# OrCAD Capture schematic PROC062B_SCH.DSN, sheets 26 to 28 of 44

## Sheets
26 25. CURRENT MONITORING DEVICES: size C; title: CURRENT MONITORING DEVICES
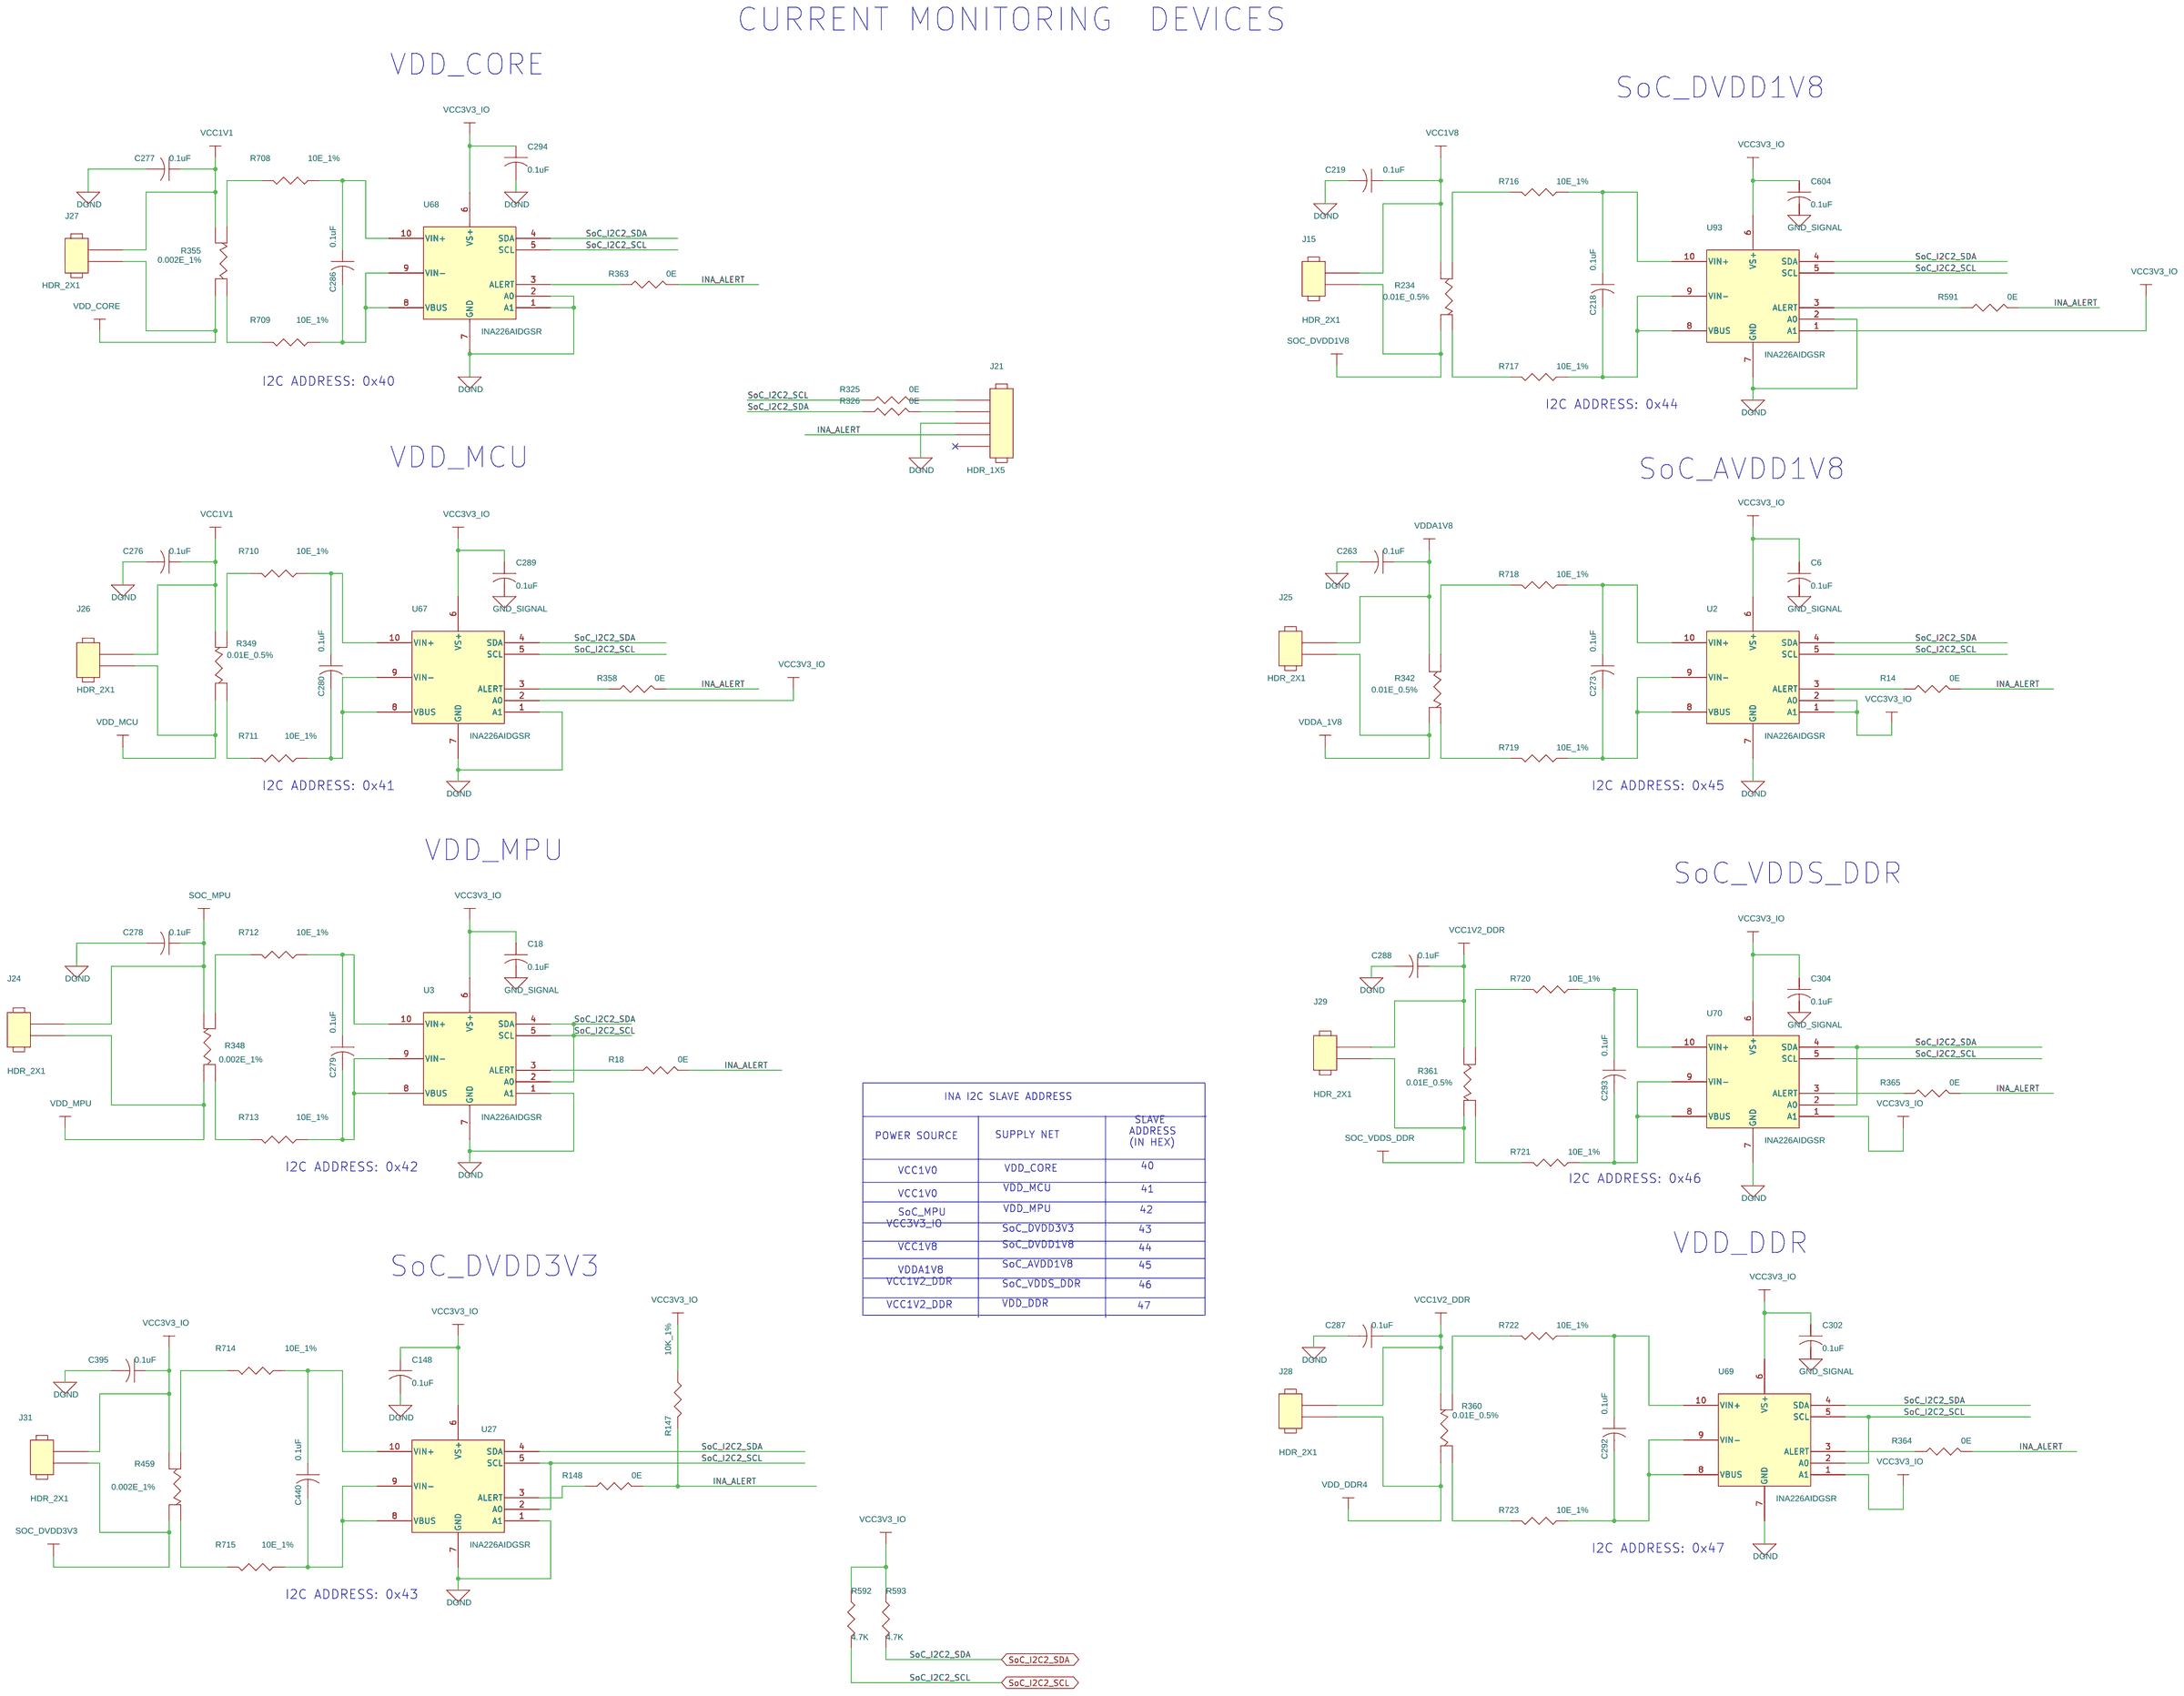
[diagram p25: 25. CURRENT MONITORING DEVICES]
27 26. XDS110 DEBUGGER: size C; title: XDS110 DEBUGGER
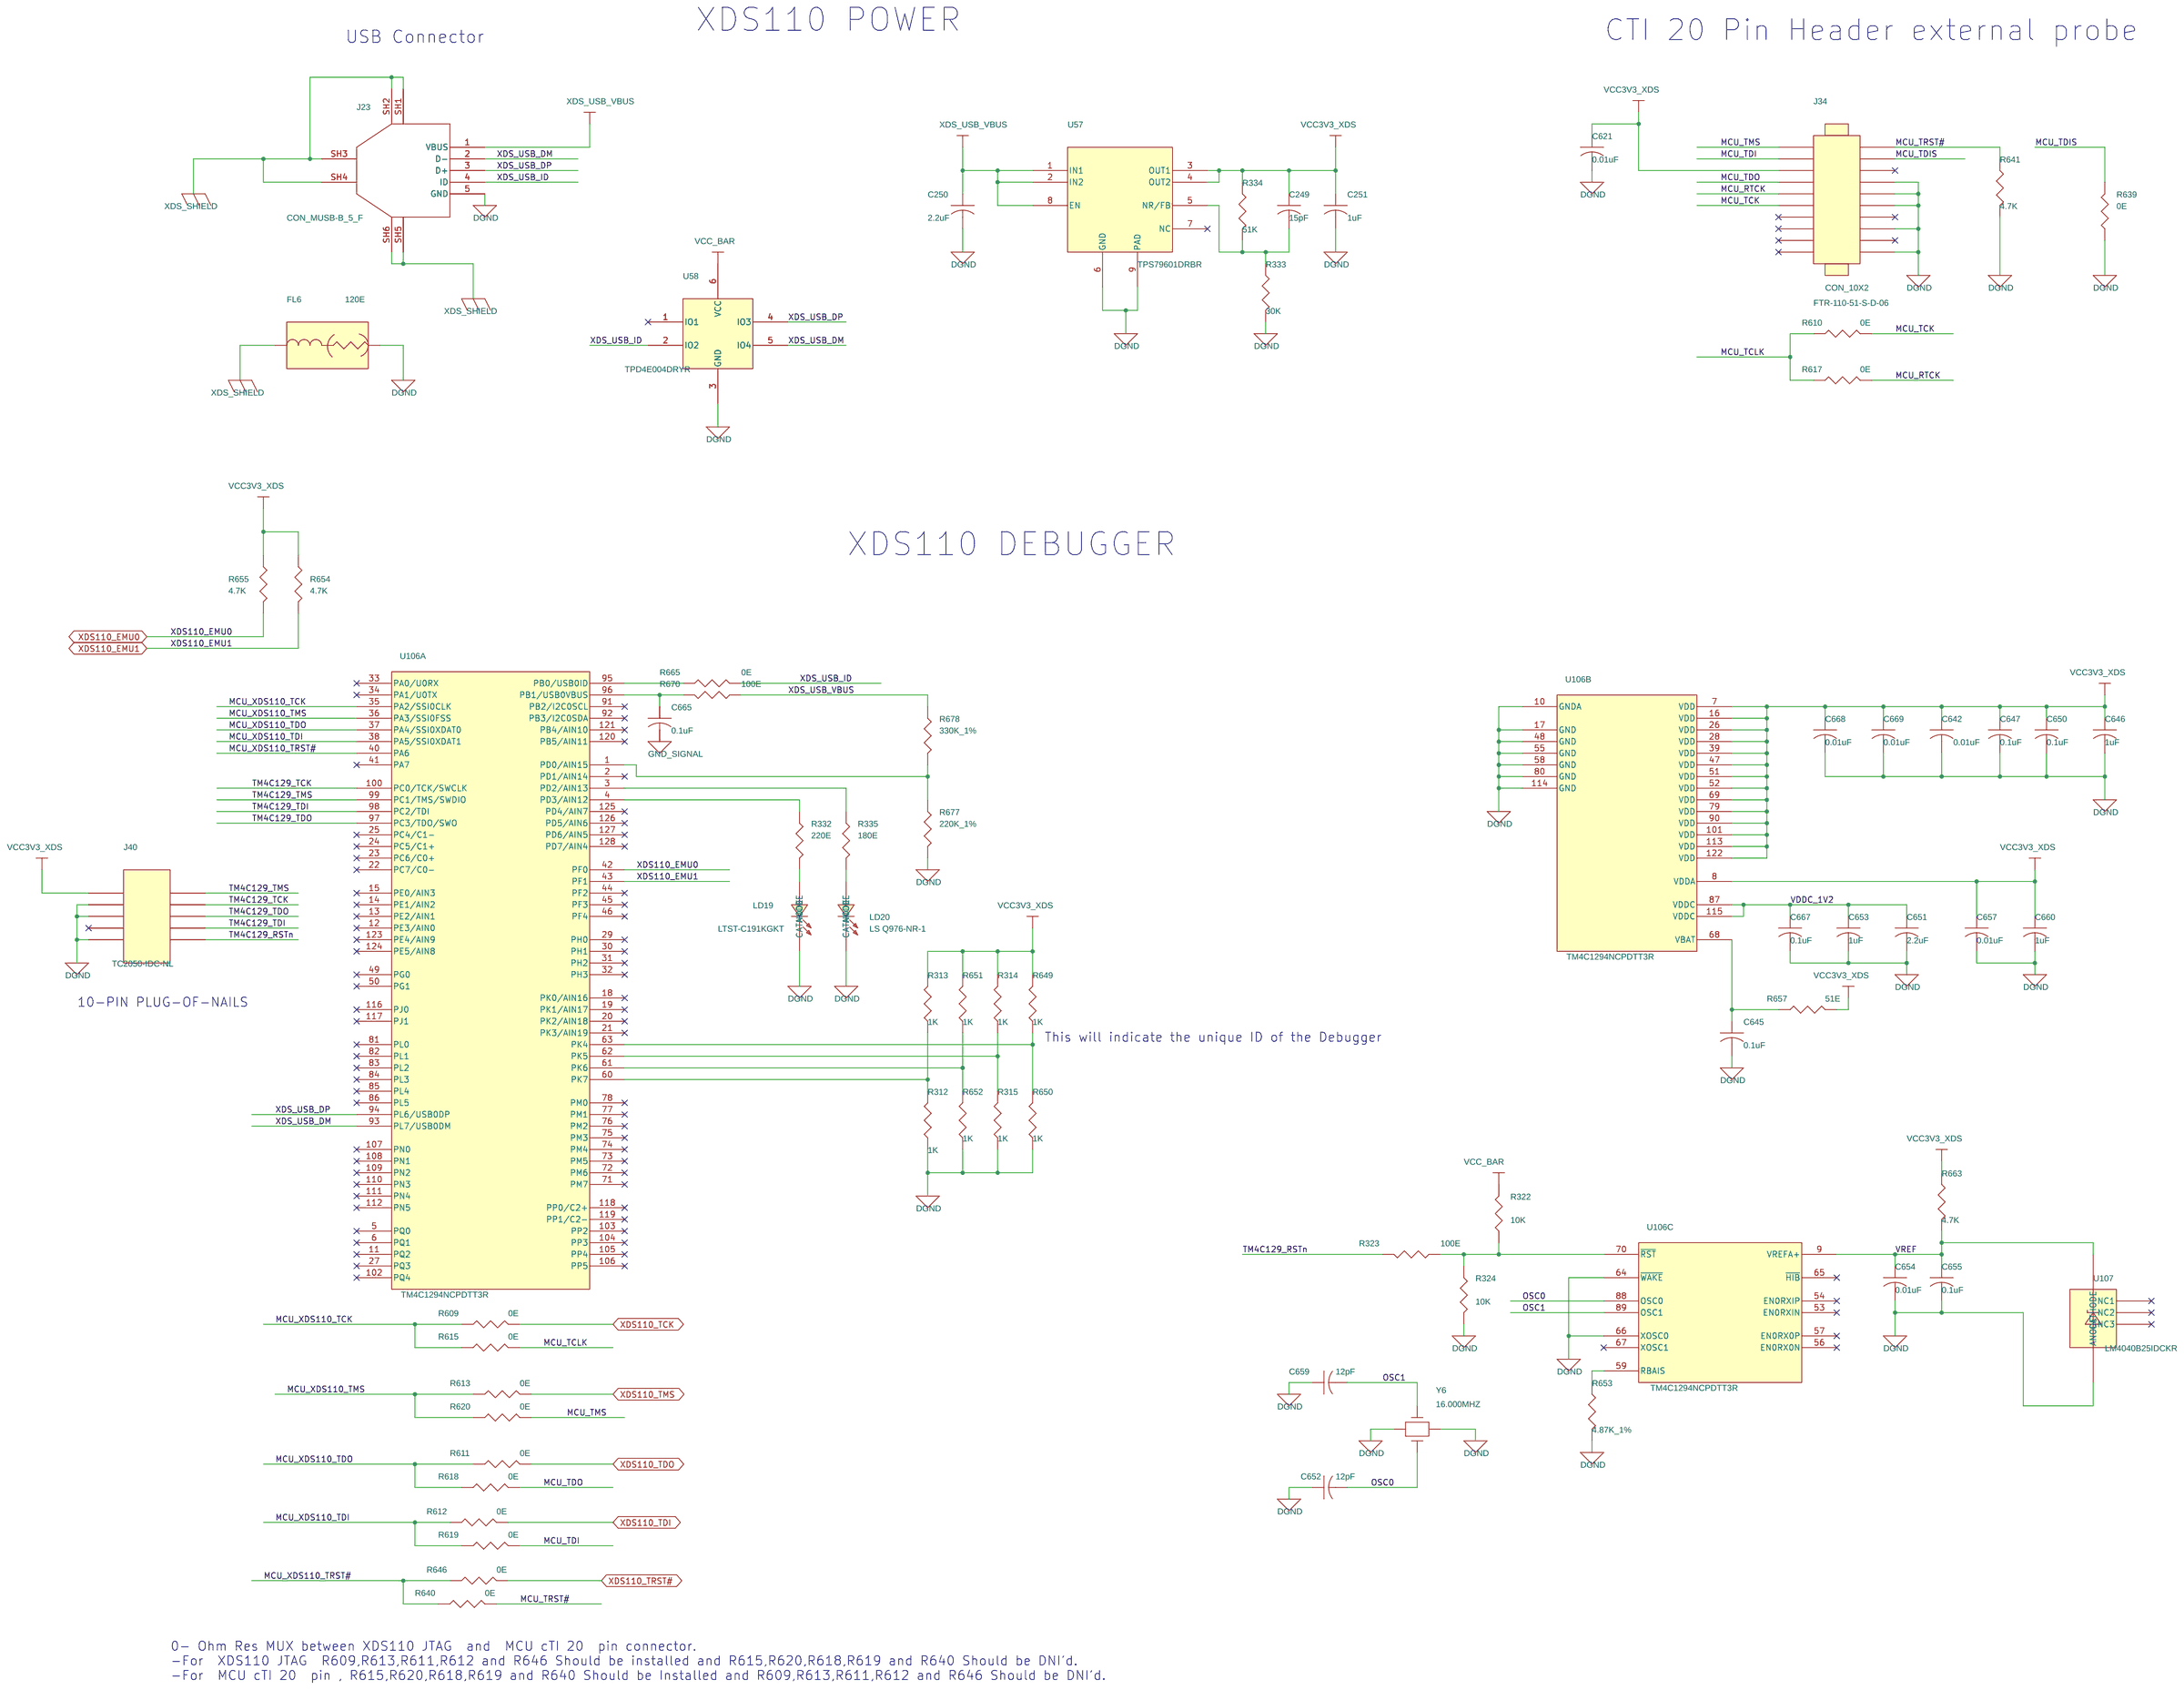
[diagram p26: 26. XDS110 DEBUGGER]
28 27. JTAG BUFFER: size C; title: JTAG BUFFER
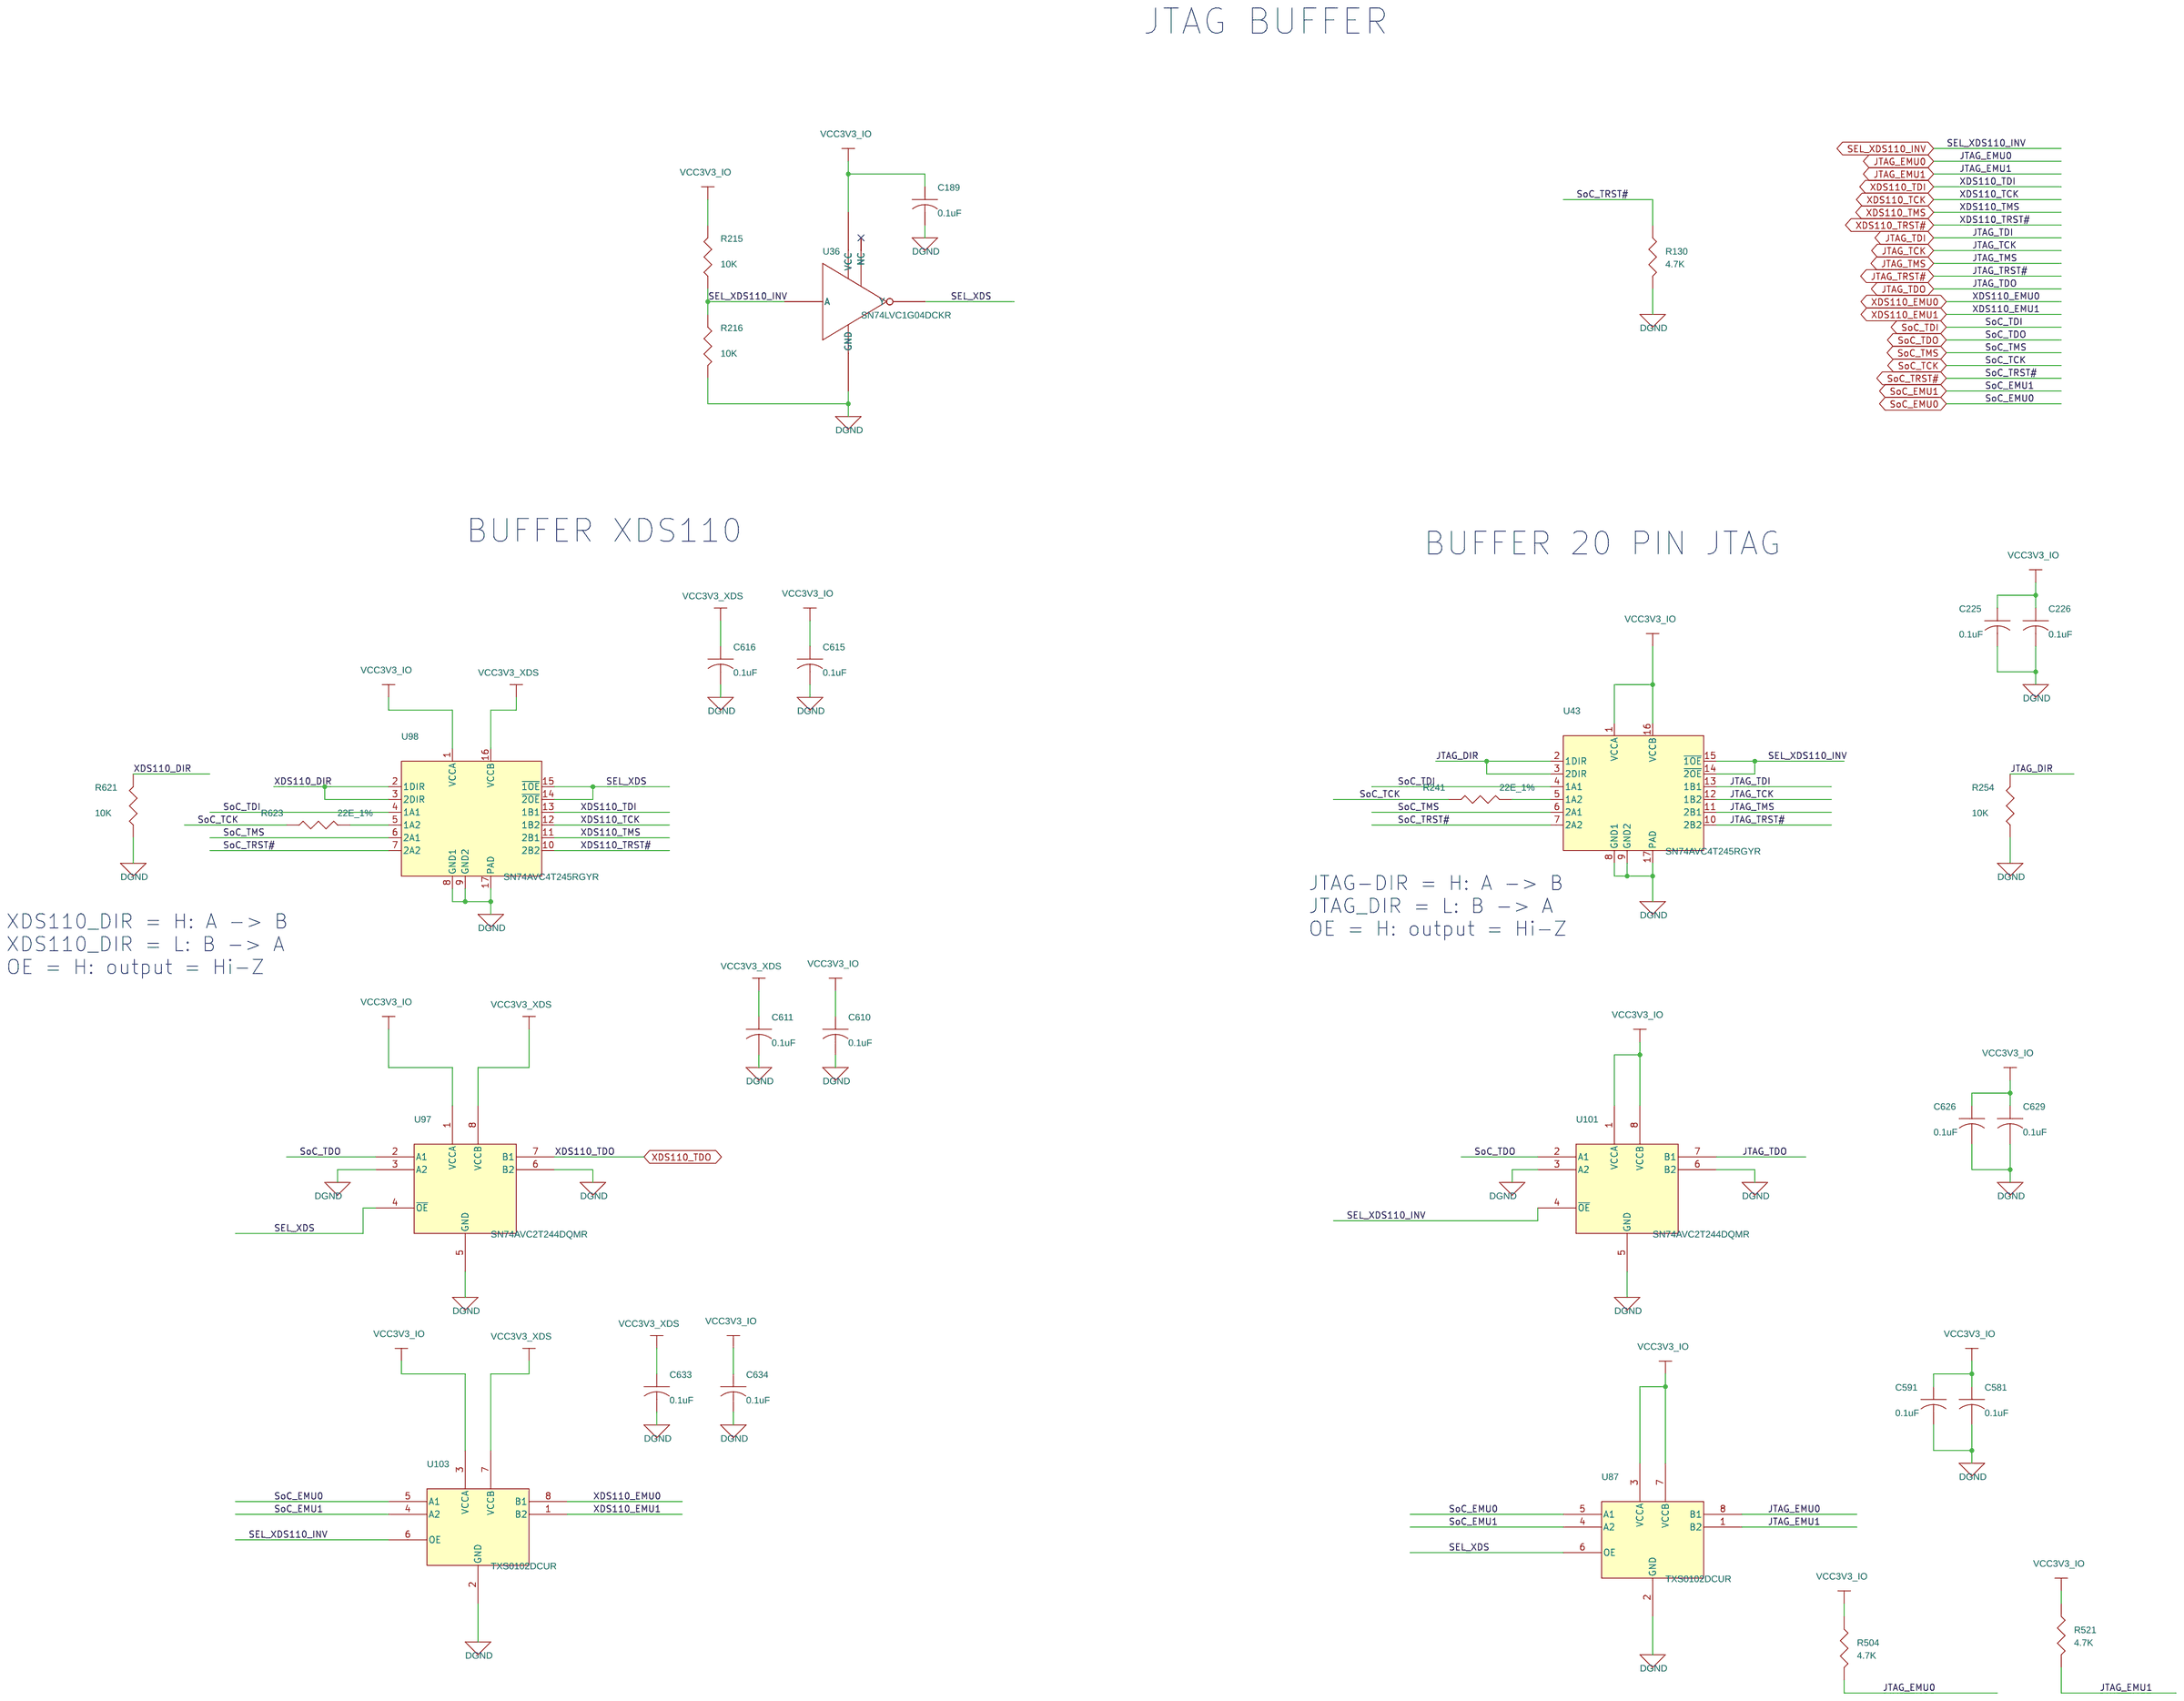
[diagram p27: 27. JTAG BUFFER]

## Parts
sheet 25. CURRENT MONITORING DEVICES
C6  0.1uF  [CAP0201_0-5]
C18  0.1uF  [CAP0201_0-5]
C148  0.1uF  [CAP0201_0-5]
C218  0.1uF  [CAP0201_0-5]
C219  0.1uF  [CAP0201_0-5]
C263  0.1uF  [CAP0201_0-5]
C273  0.1uF  [CAP0201_0-5]
C276  0.1uF  [CAP0201_0-5]
C277  0.1uF  [CAP0201_0-5]
C278  0.1uF  [CAP0201_0-5]
C279  0.1uF  [CAP0201_0-5]
C280  0.1uF  [CAP0201_0-5]
C286  0.1uF  [CAP0201_0-5]
C287  0.1uF  [CAP0201_0-5]
C288  0.1uF  [CAP0201_0-5]
C289  0.1uF  [CAP0201_0-5]
C292  0.1uF  [CAP0201_0-5]
C293  0.1uF  [CAP0201_0-5]
C294  0.1uF  [CAP0201_0-5]
C302  0.1uF  [CAP0201_0-5]
C304  0.1uF  [CAP0201_0-5]
C395  0.1uF  [CAP0201_0-5]
C440  0.1uF  [CAP0201_0-5]
C604  0.1uF  [CAP0201_0-5]
J15  HDR_2X1  [HDR_2X1_100_S_T_10-8]
J21  HDR_1X5  [HDR_5X1_100_S_T_11-2]
J24  HDR_2X1  [HDR_2X1_100_S_T_10-8]
J25  HDR_2X1  [HDR_2X1_100_S_T_10-8]
J26  HDR_2X1  [HDR_2X1_100_S_T_10-8]
J27  HDR_2X1  [HDR_2X1_100_S_T_10-8]
J28  HDR_2X1  [HDR_2X1_100_S_T_10-8]
J29  HDR_2X1  [HDR_2X1_100_S_T_10-8]
J31  HDR_2X1  [HDR_2X1_100_S_T_10-8]
R14  0E  [RES0402_0-5]
R18  0E  [RES0402_0-5]
R147  10K_1%  [RES0402_0-5]
R148  0E  [RES0402_0-5]
R234  0.01E_0.5%  [RES1206-4TERM_0-75]
R325  0E  [RES0402_0-5]
R326  0E  [RES0402_0-5]
R342  0.01E_0.5%  [RES1206-4TERM_0-75]
R348  0.002E_1%  [RES2512-4TERM_0-75]
R349  0.01E_0.5%  [RES1206-4TERM_0-75]
R355  0.002E_1%  [RES2512-4TERM_0-75]
R358  0E  [RES0402_0-5]
R360  0.01E_0.5%  [RES1206-4TERM_0-75]
R361  0.01E_0.5%  [RES1206-4TERM_0-75]
R363  0E  [RES0402_0-5]
R364  0E  [RES0402_0-5]
R365  0E  [RES0402_0-5]
R459  0.002E_1%  [RES2512-4TERM_0-75]
R591  0E  [RES0402_0-5]
R592  4.7K  [RES0402]
R593  4.7K  [RES0402]
R708  10E_1%  [RES0402_0-5]
R709  10E_1%  [RES0402_0-5]
R710  10E_1%  [RES0402_0-5]
R711  10E_1%  [RES0402_0-5]
R712  10E_1%  [RES0402_0-5]
R713  10E_1%  [RES0402_0-5]
R714  10E_1%  [RES0402_0-5]
R715  10E_1%  [RES0402_0-5]
R716  10E_1%  [RES0402_0-5]
R717  10E_1%  [RES0402_0-5]
R718  10E_1%  [RES0402_0-5]
R719  10E_1%  [RES0402_0-5]
R720  10E_1%  [RES0402_0-5]
R721  10E_1%  [RES0402_0-5]
R722  10E_1%  [RES0402_0-5]
R723  10E_1%  [RES0402_0-5]
U2  INA226AIDGSR  [MSOP10_19-68_120X120_1-1]
U3  INA226AIDGSR  [MSOP10_19-68_120X120_1-1]
U27  INA226AIDGSR  [MSOP10_19-68_120X120_1-1]
U67  INA226AIDGSR  [MSOP10_19-68_120X120_1-1]
U68  INA226AIDGSR  [MSOP10_19-68_120X120_1-1]
U69  INA226AIDGSR  [MSOP10_19-68_120X120_1-1]
U70  INA226AIDGSR  [MSOP10_19-68_120X120_1-1]
U93  INA226AIDGSR  [MSOP10_19-68_120X120_1-1]
sheet 26. XDS110 DEBUGGER
C249  15pF  [CAP0402_0-75]
C250  2.2uF  [CAP0402_0-75]
C251  1uF  [CAP0402_0-75]
C621  0.01uF  [CAP0201_0-5]
C642  0.01uF  [CAP0201_0-5]
C645  0.1uF  [CAP0201_0-5]
C646  1uF  [CAP0402_0-75]
C647  0.1uF  [CAP0201_0-5]
C650  0.1uF  [CAP0201_0-5]
C651  2.2uF  [CAP0402_0-75]
C652  12pF  [CAP0402_0-75]
C653  1uF  [CAP0402_0-75]
C654  0.01uF  [CAP0201_0-5]
C655  0.1uF  [CAP0201_0-5]
C657  0.01uF  [CAP0201_0-5]
C659  12pF  [CAP0402_0-75]
C660  1uF  [CAP0402_0-75]
C665  0.1uF  [CAP0201_0-5]
C667  0.1uF  [CAP0201_0-5]
C668  0.01uF  [CAP0201_0-5]
C669  0.01uF  [CAP0201_0-5]
FL6  120E  [EMIFIL_BLM15A_0402_0-6]
J23  CON_MUSB-B_5_F  [CON_MUSBB5_1051640001_S_R_S_2-5]
J34  CON_10X2  [CON_10X2_FTR-110-51-S-D_P_S_S]
J40  TC2050-IDC-NL  [CON_2X5_TC2050-IDC-430-NL_T]
LD19  LTST-C191KGKT  [LED_0603]
LD20  LS Q976-NR-1  [LED_0603_0-8]
R312  1K  [RES0201]
R313  1K  [RES0201]
R314  1K  [RES0201]
R315  1K  [RES0201]
R322  10K  [RES0402_0-5]
R323  100E  [RES0402_0-5]
R324  10K  [RES0402_0-5]
R332  220E  [RES0402_0-5]
R333  30K  [RES0402_0-5]
R334  51K  [RES0402_0-5]
R335  180E  [RES0402]
R609  0E  [RES0402_0-5]
R610  0E  [RES0402_0-5]
R611  0E  [RES0402_0-5]
R612  0E  [RES0402_0-5]
R613  0E  [RES0402_0-5]
R615  0E  [RES0402_0-5]
R617  0E  [RES0402_0-5]
R618  0E  [RES0402_0-5]
R619  0E  [RES0402_0-5]
R620  0E  [RES0402_0-5]
R639  0E  [RES0402_0-5]
R640  0E  [RES0402_0-5]
R641  4.7K  [RES0402]
R646  0E  [RES0402_0-5]
R649  1K  [RES0201]
R650  1K  [RES0201]
R651  1K  [RES0201]
R652  1K  [RES0201]
R653  4.87K_1%  [RES0402]
R654  4.7K  [RES0402]
R655  4.7K  [RES0402]
R657  51E  [RES0402]
R663  4.7K  [RES0402]
R665  0E  [RES0402_0-5]
R670  100E  [RES0402_0-5]
R677  220K_1%  [RES0402_0-5]
R678  330K_1%  [RES0402_0-5]
U57  TPS79601DRBR  [SON8_25-59_130X130_1]
U58  TPD4E004DRYR  [SON6_19-68_60X45]
U106  TM4C1294NCPDTT3R  [TQFP128_15-74_550X550_1-2]  (sections A,B,C)
U107  LM4040B25IDCKR  [SC70-5_1-1]
Y6  16.000MHZ  [XTAL4_NX3225GA_130X100_SMD_0-9]
sheet 27. JTAG BUFFER
C189  0.1uF  [CAP0201_0-5]
C225  0.1uF  [CAP0201_0-5]
C226  0.1uF  [CAP0201_0-5]
C581  0.1uF  [CAP0201_0-5]
C591  0.1uF  [CAP0201_0-5]
C610  0.1uF  [CAP0201_0-5]
C611  0.1uF  [CAP0201_0-5]
C615  0.1uF  [CAP0201_0-5]
C616  0.1uF  [CAP0201_0-5]
C626  0.1uF  [CAP0201_0-5]
C629  0.1uF  [CAP0201_0-5]
C633  0.1uF  [CAP0201_0-5]
C634  0.1uF  [CAP0201_0-5]
R130  4.7K  [RES0402]
R215  10K  [RES0402_0-5]
R216  10K  [RES0402_0-5]
R241  22E_1%  [RES0402]
R254  10K  [RES0402_0-5]
R504  4.7K  [RES0402]
R521  4.7K  [RES0402]
R621  10K  [RES0402_0-5]
R623  22E_1%  [RES0402]
U36  SN74LVC1G04DCKR  [SC70-5]
U43  SN74AVC4T245RGYR  [QFN16_19-68_160X140]
U87  TXS0102DCUR  [VSSOP8_19-68_85X95_0-9]
U97  SN74AVC2T244DQMR  [X2SON8_15-74_70X50]
U98  SN74AVC4T245RGYR  [QFN16_19-68_160X140]
U101  SN74AVC2T244DQMR  [X2SON8_15-74_70X50]
U103  TXS0102DCUR  [VSSOP8_19-68_85X95_0-9]

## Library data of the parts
C6 C18 C148 C189 C225 C226 C289 C294 C302 C304 C581 C591 C604 C610 C611 C615 C616 C626 C629 C633 C634 C645 C647 C650 C655 C665 C667 = CAP: CAP CERAMIC 0.1uF 16V 10% X5R 0201; Chkd/date: MANIRAJA/120218; Crtd /date: MANIRAJA/120218; Custom_Duty: 15%; Customs_HS_Code: 85322990; Distributor_name: DIGIKEY; Distributor_part_number: 490-16742-1-ND; Height: 0.33MM; Mfr_name: MURATA; Mfr_part_number: GRM033R61C104KE84J; Mistral Part No: 120009030072-R; Package: 0201; Part_type: CAPACITORS\CERAMIC; Project: TI_MAXIE_CPB; RoHS: RoHS; Temperature: -55°C+85°C; Tolerance: 10%; Voltage: 16V; Wattage: NA; Weight: 0.33mg; Datasheet: Y:\MIS_DATABASE\DATASHEETS\CAPACITORS\GRM033R61C104KE84.PDF
C218 C219 C263 C273 C276-C280 C286-C288 C292 C293 C395 C440 = CAP: CAP CERAMIC 0.1uF 16V 10% X5R 0201; Chkd/date: MANIRAJA/120218; Crtd /date: MANIRAJA/120218; Custom_Duty: 15%; Customs_HS_Code: 85322990; Distributor_name: DIGIKEY; Distributor_part_number: 490-16742-1-ND; Height: 0.33MM; Mfr_name: MURATA; Mfr_part_number: GRM033R61C104KE84J; Mistral Part No: 120009030072-R; PART_NUMBER: EC01002; Package: 0201; Part_type: CAPACITORS\CERAMIC; Project: TI_MAXIE_CPB; RoHS: RoHS; Taser_part_number: EC01002; Temperature: -55°C+85°C; Tolerance: 10%; Voltage: 16V; Wattage: NA; Weight: 0.33mg; Datasheet: Y:\MIS_DATABASE\DATASHEETS\CAPACITORS\GRM033R61C104KE84.PDF
J15 J24-J29 J31 = HEADER_2X1: CON HDR 2X1 2.54MM PITCH ST TH; Chkd/date: VASANTHA/060117; Crtd /date: MAZHAR/280405; Custom_Duty: 24%; Customs_HS_Code: 85369090; Distributor_name: DIGIKEY; Distributor_part_number: WM4000-ND; Footprint Path: Y:\MIS_DATABASE\Library\ALTIUM_TOOL\PCB_FOOTPRINTS\Altium_Footprint_Lib.PcbLib; Height: 10.79MM; Library Path: Y:\MIS_DATABASE\Library\ALTIUM_TOOL\SCHEMATICS_PARTS\MS_Connector_Library.schlib; Mfr_name: MOLEX; Mfr_part_number: 22-03-2021; Mistral Part No: 150009030246-R; Package: THRU-HOLE; Part_type: CONNECTOR\HEADERS; Project: FPGA EXTENDER CARD; RoHS: RoHS; Temperature: -0°C+75°C; Tolerance: NA; Voltage: NA; Wattage: NA; Weight: 139gm; Datasheet: Y:\MIS_DATABASE\DATASHEETS\CONNECTORS\HEADER_X4030.PDF
J21 = HEADER_5X1: CON HDR 1X5 2.54MM PITCH ST TH; Chkd/date: VASANTHA/310117; Crtd /date: MAZHAR/280405; Custom_Duty: 24%; Customs_HS_Code: 85369090; Distributor_name: DIGIKEY; Distributor_part_number: WM4003-ND; Height: 11.17MM; Mfr_name: MOLEX; Mfr_part_number: 22-03-2051; Mistral Part No: 150009030262-R; Package: THRU-HOLE; Part_type: CONNECTOR\HEADERS; Project: HSWD; RoHS: RoHS; Temperature: NA; Tolerance: NA; Voltage: NA; Wattage: NA; Weight: 343mg; Datasheet: Y:\MIS_DATABASE\DATASHEETS\CONNECTORS\MOLEX022032021.PDF
R14 R18 R148 R325 R326 R358 R363-R365 R591 R609-R613 R615 R617-R620 R639 R640 R646 R665 = RESISTOR: RES 0E 1/16W 0402; Chkd/date: VASANTHA/201216; Crtd /date: MUDDU/190810; Custom_Duty: 15%; Customs_HS_Code: 85332119; Distributor_name: DIGIKEY; Distributor_part_number: 541-0.0JCT-ND; Footprint Path: Y:\MIS_DATABASE\Library\ALTIUM_TOOL\PCB_FOOTPRINTS\Altium_Footprint_Lib.PcbLib; Height: 0.40MM; Library Path: Y:\MIS_DATABASE\Library\ALTIUM_TOOL\SCHEMATICS_PARTS\MS_DISCRETE_Library.schlib; Mfr_name: VISHAY; Mfr_part_number: CRCW04020000Z0ED; Mistral Part No: 110010080019-P; Package: 0402; Part_type: RESISTORS\FIXED; Project: PB_BUGBASE; RoHS: Pb-Free; Temperature: -55°C+155°C; Tolerance: NA; Voltage: NA; Wattage: 1/16W; Weight: 0.65g/1000pcs; Datasheet: Y:\MIS_DATABASE\DATASHEETS\RESISTORS\CRCW0603.PDF
R147 = RESISTOR: RES 10K 1/16W 1% 0402; Chkd/date: VASANTHA/201216; Crtd /date: GEETHA/290506; Custom_Duty: 15%; Customs_HS_Code: 85332119; Distributor_name: DIGIKEY; Distributor_part_number: 311-10.0KLRTR-ND; Footprint Path: Y:\MIS_DATABASE\Library\ALTIUM_TOOL\PCB_FOOTPRINTS\Altium_Footprint_Lib.PcbLib; Height: 0.40MM; Library Path: Y:\MIS_DATABASE\Library\ALTIUM_TOOL\SCHEMATICS_PARTS\MS_DISCRETE_Library.schlib; Mfr_name: YAGEO AMERICA; Mfr_part_number: RC0402FR-0710KL; Mistral Part No: 110009030220-P; Package: 0402; Part_type: RESISTORS\FIXED; Project: VOCERA; RoHS: Pb-Free; Temperature: -55°C+155°C; Tolerance: 1%; Voltage: NA; Wattage: 1/16W; Weight: 0.65mg; Datasheet: Y:\MIS_DATABASE\DATASHEETS\RESISTORS\YAGEO-RC0402.PDF
R234 R342 R349 R360 R361 = RESISTOR-4TERM: RES 0.01E 1/2W 0.5% 4-TERM1206; Chkd/date: MANIRAJA/260917; Crtd /date: MANIRAJA/260917; Custom_Duty: 15%; Customs_HS_Code: 85332119; Distributor_name: DIGIKEY; Distributor_part_number: LVK12R010DERCT-ND; Height: 0.65MM; Mfr_name: OHMITE; Mfr_part_number: LVK12R010DER; Mistral Part No: 110017090009-R; Package: 1206-4TERM; Part_type: RESISTORS\FIXED; Project: TI_MAXIE_CPB; RoHS: RoHS; Temperature: -40°C+125°C; Tolerance: 0.5%; Voltage: NA; Wattage: 1/2W; Weight: 16.2mg; Datasheet: Y:\MIS_DATABASE\DATASHEETS\RESISTORS\LVK-SERIES.PDF
R348 R355 R459 = RESISTOR-4TERM: RES 0.002E 2W 1% 4-TERM2512; Chkd/date: MANIRAJA/260917; Crtd /date: MANIRAJA/260917; Custom_Duty: 15%; Customs_HS_Code: 85332119; Distributor_name: DIGIKEY; Distributor_part_number: LVK25R002FERCT-ND; Height: 0.70MM; Mfr_name: OHMITE; Mfr_part_number: LVK25R002FER; Mistral Part No: 110017090010-R; Package: 2512-4TERM; Part_type: RESISTORS\FIXED; Project: TI_MAXIE_CPB; RoHS: RoHS; Temperature: -40°C+125°C; Tolerance: 1%; Voltage: NA; Wattage: 2W; Weight: NA; Datasheet: Y:\MIS_DATABASE\DATASHEETS\RESISTORS\LVK-SERIES.PDF
R130 R504 R521 R592 R593 R641 R654 R655 R663 = RESISTOR: RES 4.7K 1/16W 5% 0402; Chkd/date: VASANTHA/130516; Crtd /date: VASANTHA/130516; Custom_Duty: 15%; Customs_HS_Code: 85332119; Distributor_name: DIGIKEY; Distributor_part_number: 311-4.7KJRCT-ND; Height: 0.55MM; Mfr_name: YAGEO AMERICA; Mfr_part_number: RC0402JR-074K7L; Mistral Part No: 110009030792-R; Package: 0402; Part_type: RESISTORS\FIXED; Project: TMDXCSK368; RoHS: RoHS; Temperature: -55°C+155°C; Tolerance: 5%; Voltage: NA; Wattage: 1/16W; Weight: NA; Datasheet: Y:\MIS_DATABASE\DATASHEETS\RESISTORS\YAGEO-RC0402.PDF
R708-R723 = RESISTOR: RES 10E 1/16W 1% 0402; Chkd/date: MANIRAJA/070218; Crtd /date: ALVY/070218; Custom_Duty: 15%; Customs_HS_Code: 85332119; Distributor_name: DIGIKEY; Distributor_part_number: 311-10.0LRCT-ND; Height: 0.40MM; Mfr_name: YAGEO AMERICA; Mfr_part_number: RC0402FR-0710RL; Mistral Part No: 110018020004-R; Package: 0402; Part_type: RESISTORS\FIXED; Project: TI_MAXIE_CPB; RoHS: RoHS; Temperature: -55°C+155°C; Tolerance: 1%; Voltage: NA; Wattage: 1/16W; Weight: 0.65mg; Datasheet: Y:\MIS_DATABASE\DATASHEETS\RESISTORS\YAGEO-RC0402.PDF
U2 U3 U27 U67-U70 U93 = INA226AIDGS_MSOP10: IC BI-DIRECTIONAL CURRENT MONITER MSOP10; Chkd/date: MANIRAJA/050417; Crtd /date: MANIRAJA/050417; Custom_Duty: 15%; Customs_HS_Code: 85423100; Distributor_name: DIGIKEY; Distributor_part_number: 296-29034-1-ND; Footprint Path: Y:\MIS_DATABASE\Library\ALTIUM_TOOL\PCB_FOOTPRINTS\Altium_Footprint_Lib.PcbLib; Height: 1.10MM; Library Path: Y:\MIS_DATABASE\Library\ALTIUM_TOOL\SCHEMATICS_PARTS\MS_MISCINTERFACE_Library.schlib; Mfr_name: TEXAS INSTRUMENTS; Mistral Part No: 141011080019-R; Package: MSOP10; Part_type: ICS\INTERFACE; Project: DM385EVM_BASE-BOARD; RoHS: RoHS; Temperature: -40°C+125°C; Tolerance: NA; Voltage: NA; Wattage: NA; Weight: NA; Datasheet: Y:\MIS_DATABASE\DATASHEETS\ICS\INTERFACE\INA226.PDF
C249 = CAP: CAP CERAMIC 15pF 25V 5% C0G(NP0) 0402; Chkd/date: MANIRAJA/070220; Crtd /date: ALVY/070220; Custom_Duty: 15%; Customs_HS_Code: 85322990; Distributor_name: DIGIKEY; Distributor_part_number: 399-15298-1-ND; Footprint Path: Y:\MIS_DATABASE\Library\ALTIUM_TOOL\PCB_FOOTPRINTS\Altium_Footprint_Lib.PcbLib; Height: 0.55MM; Library Path: Y:\MIS_DATABASE\Library\ALTIUM_TOOL\SCHEMATICS_PARTS\MS_DISCRETE_Library.schlib; Mfr_name: KEMET; Mfr_part_number: C0402C150J3GAC7867; Mistral Part No: 120020020004-R; Package: 0402; Part_type: CAPACITORS\CERAMIC; Project: TI_MAXIE_CPB; RoHS: RoHS; Temperature: -55°C+125°C; Tolerance: 5%; Voltage: 25V; Wattage: NA; Weight: 0.65mg; Datasheet: Y:\MIS_DATABASE\DATASHEETS\CAPACITORS\KEMET-C0G_SERIES.PDF
C250 C651 = CAP: CAP CERAMIC 2.2uF 10V 20% X5R 0402; Chkd/date: MANIRAJA/240118; Crtd /date: MANIRAJA/240118; Custom_Duty: 15%; Customs_HS_Code: 85322990; Distributor_name: DIGIKEY; Distributor_part_number: 490-12254-1-ND; Height: 0.55MM; Mfr_name: MURATA; Mfr_part_number: GRT155R61A225ME01D; Mistral Part No: 120018010016-R; Package: 0402; Part_type: CAPACITORS\CERAMIC; Project: TI_MAXIE_CPB; RoHS: RoHS; Temperature: -55°C+85°C; Tolerance: 20%; Voltage: 10V; Wattage: NA; Weight: 0.65mg; Datasheet: Y:\MIS_DATABASE\DATASHEETS\CAPACITORS\GRT155R61A225ME01.PDF
C251 C646 C653 C660 = CAP: CAP CERAMIC 1uF 16V 20% X5R 0402; Chkd/date: MANIRAJA/150218; Crtd /date: ALVY/150218; Custom_Duty: 15%; Customs_HS_Code: 85322990; Distributor_name: DIGIKEY; Distributor_part_number: 587-5514-1-ND; Footprint Path: Y:\MIS_DATABASE\Library\ALTIUM_TOOL\PCB_FOOTPRINTS\Altium_Footprint_Lib.PcbLib; Height: 0.55MM; Library Path: Y:\MIS_DATABASE\Library\ALTIUM_TOOL\SCHEMATICS_PARTS\MS_DISCRETE_Library.schlib; Mfr_name: TAIYO YUDEN; Mfr_part_number: EMK105BJ105MV-F; Mistral Part No: 120018020006-R; Package: 0402; Part_type: CAPACITORS\CERAMIC; Project: TI_MAXIE_CPB; RoHS: RoHS; Temperature: -55°C+85°C; Tolerance: 20%; Voltage: 16V; Wattage: NA; Weight: 0.65mg; Datasheet: Y:\MIS_DATABASE\DATASHEETS\CAPACITORS\EMK105BJ105MV-F.PDF
C621 C642 C654 C657 C668 C669 = CAP: CAP CERAMIC 0.01uF 25V 10% X5R 0201; Chkd/date: MANIRAJA/230118; Crtd /date: MANIRAJA/230118; Custom_Duty: 15%; Customs_HS_Code: 85322990; Distributor_name: DIGIKEY; Distributor_part_number: GRM033R61E103KA12J-ND; Height: 0.33MM; Mfr_name: MURATA; Mfr_part_number: GRM033R61E103KA12J; Mistral Part No: 120018010007-R; Package: 0201; Part_type: CAPACITORS\CERAMIC; Project: TI_MAXIE_CPB; RoHS: RoHS; Temperature: -55°C+85°C; Tolerance: 10%; Voltage: 25V; Wattage: NA; Weight: 0.33mg; Datasheet: Y:\MIS_DATABASE\DATASHEETS\CAPACITORS\GRM033R61E103KA12.PDF
C652 C659 = CAP: CAP CERAMIC 12pF 50V 5% C0G(NP0) 0402; Chkd/date: MANIRAJA/070220; Crtd /date: ALVY/070220; Custom_Duty: 15%; Customs_HS_Code: 85322990; Distributor_name: DIGIKEY; Distributor_part_number: 1276-1178-1-ND; Footprint Path: Y:\MIS_DATABASE\Library\ALTIUM_TOOL\PCB_FOOTPRINTS\Altium_Footprint_Lib.PcbLib; Height: 0.55MM; Library Path: Y:\MIS_DATABASE\Library\ALTIUM_TOOL\SCHEMATICS_PARTS\MS_DISCRETE_Library.schlib; Mfr_name: SAMSUNG; Mfr_part_number: CL05C120JB5NNNC; Mistral Part No: 120020020003-R; Package: 0402; Part_type: CAPACITORS\CERAMIC; Project: TI_MAXIE_CPB; RoHS: RoHS; Temperature: -55°C+125°C; Tolerance: 5%; Voltage: 50V; Wattage: NA; Weight: NA; Datasheet: Y:\MIS_DATABASE\DATASHEETS\CAPACITORS\CL05C120JB5NNNC.PDF
FL6 = EMIFILTER_IND: FERRITE CHIP 120E 1.3A 0402; Chkd/date: VASANTHA/010117; Crtd /date: CHAITHANYA/150312; Custom_Duty: 24%; Customs_HS_Code: 85437099; Distributor_name: DIGIKEY; Distributor_part_number: 490-5203-1-ND; Footprint Path: Y:\MIS_DATABASE\Library\ALTIUM_TOOL\PCB_FOOTPRINTS\Altium_Footprint_Lib.PcbLib; Height: 0.55MM; Library Path: Y:\MIS_DATABASE\Library\ALTIUM_TOOL\SCHEMATICS_PARTS\MS_FILTER_Library.schlib; Mfr_name: MURATA; Mfr_part_number: BLM15PD121SN1; Mistral Part No: 130012030043-R; Package: 0402; Part_type: MISC\FILTER; Project: GEN_3-8; RoHS: RoHS; Temperature: -55°C+125°C; Tolerance: 25%; Voltage: NA; Wattage: NA; Weight: 0.65mg; Datasheet: Y:\MIS_DATABASE\DATASHEETS\DISCRETES\INDUCTORS\BLM18K-SERIES.PDF
J23 = CON_MUSB-B_5_1051640001: CON MICRO USB-B TYPE 5POS FEMALE RT SMD; Chkd/date: MANIRAJA/230817; Crtd /date: MANIRAJA/230817; Custom_Duty: 24%; Customs_HS_Code: 85369090; Distributor_name: DIGIKEY; Distributor_part_number: WM11263CT-ND; Height: 2.45MM; Mfr_name: MOLEX; Mfr_part_number: 1051640001; Mistral Part No: 150017080018-R; Package: SMD; Part_type: CONNECTOR\USB; Project: TI_MAXIE_CPB; RoHS: RoHS; Temperature: -35°C+85°C; Tolerance: NA; Voltage: NA; Wattage: NA; Weight: 234mg; Datasheet: Y:\MIS_DATABASE\DATASHEETS\CONNECTORS\1051640001.PDF
J34 = CON_10X2: CON 10X2 1.27MM PITCH MALE SMD; Chkd/date: BAVISH/050911; Crtd /date: CHAITHANYA/050811; Custom_Duty: 24%; Customs_HS_Code: 85369090; Distributor_name: DIGIKEY; Distributor_part_number: FTR-110-51-S-D-06-ND; Height: 7.37MM; Mfr_name: SAMTEC; Mfr_part_number: FTR-110-51-S-D-06; Mistral Part No: 150011090001-R; Package: SMD; Part_type: CONNECTOR\MISCELLANEOUS; Project: GEMYC; RoHS: RoHS; Temperature: -55°C+105°C; Tolerance: NA; Voltage: NA; Wattage: NA; Weight: NA; Datasheet: Y:\MIS_DATABASE\DATASHEETS\CONNECTORS\FTR-SERIES1.PDF
J40 = CON_5X2: ACCESSORIE CABLE TAG CONNECT IN CIRCUIT 10POS WITH IDC CONNECTOR; Chkd/date: VASANTHA/031215; Crtd /date: VASANTHA/031215; Distributor_name: NA; Distributor_part_number: NA; Height: NA; Mfr_name: TAG CONNECT; Mistral Part No: 170015120001; Package: NA; Part_type: CABLE\ACCESSORIES; Project: ADI_SMLT; Temperature: NA; Tolerance: NA; Voltage: NA; Wattage: NA; Weight: NA; Datasheet: Y:\MIS_DATABASE\DATASHEETS\MISC\ACCESSORIES\TC2050-IDC-NL.PDF
LD19 = DIODE_LED: DIODE LED GREEN CLEAR 574NM 0603; Chkd/date: VASANTHA/280616; Crtd /date: VASANTHA/280616; Custom_Duty: 24%; Customs_HS_Code: 85439000; Distributor_name: DIGIKEY; Distributor_part_number: 160-1446-1-ND; Height: 0.55MM; Mfr_name: LITEON; Mistral Part No: 130016060076-R; Package: 0603; Part_type: OPTO\LED; Project: TMDXCSKCC; RoHS: RoHS; Temperature: -55°C+85°C; Tolerance: NA; Voltage: NA; Wattage: NA; Weight: NA; Datasheet: Y:\MIS_DATABASE\DATASHEETS\DISCRETES\LEDS\LTST-C191KGKT.PDF
LD20 = DIODE_LED: LED SUPER RED 0603; Chkd/date: MANIRAJA/150218; Crtd /date: ALVY/150218; Custom_Duty: 24%; Customs_HS_Code: 85437099; Distributor_name: DIGIKEY; Distributor_part_number: 475-2512-1-ND; Footprint Path: Y:\MIS_DATABASE\Library\ALTIUM_TOOL\PCB_FOOTPRINTS\Altium_Footprint_Lib.PcbLib; Height: 0.80MM; Library Path: Y:\MIS_DATABASE\Library\ALTIUM_TOOL\SCHEMATICS_PARTS\MS_OPTO_Library.schlib; Mfr_name: OSRAM; Mistral Part No: 130018020039-R; Package: 0603; Part_type: OPTO\LED; Project: TI_MAXIE_CPB; RoHS: RoHS; Temperature: -30°C+85°C; Tolerance: NA; Voltage: NA; Wattage: NA; Weight: 1.4mg; Datasheet: Y:\MIS_DATABASE\DATASHEETS\DISCRETES\LEDS\LSQ976-NR-1.PDF
R312-R315 R649-R652 = RESISTOR: RES 1K 1/20W 5% 0201; Chkd/date: JEBRAN/110815; Crtd /date: JEBRAN/110815; Custom_Duty: 15%; Customs_HS_Code: 85332119; Distributor_name: DIGIKEY; Distributor_part_number: 541-1.00KAABCT-ND; Height: 0.28MM; Mfr_name: VISHAY; Mfr_part_number: CRCW02011K00FKED; Mistral Part No: 110015080014-R; Package: 0201; Part_type: RESISTORS\FIXED; Project: OCTASIC_3000; RoHS: RoHS; Temperature: -55°C+155°C; Tolerance: 5%; Voltage: NA; Wattage: 1/20W; Weight: NA; Datasheet: Y:\MIS_DATABASE\DATASHEETS\RESISTORS\CRCW0201.PDF
R215 R216 R254 R322 R324 R621 = RESISTOR: RES 10K 1/16W 5% 0402; Chkd/date: VASANTHA/061216; Crtd /date: MAZHAR/230805; Custom_Duty: 15%; Customs_HS_Code: 85332119; Distributor_name: DIGIKEY; Distributor_part_number: 311-10KJRCT-ND; Footprint Path: Y:\MIS_DATABASE\Library\ALTIUM_TOOL\PCB_FOOTPRINTS\Altium_Footprint_Lib.PcbLib; Height: 0.40MM; Library Path: Y:\MIS_DATABASE\Library\ALTIUM_TOOL\SCHEMATICS_PARTS\MS_DISCRETE_Library.schlib; Mfr_name: YAGEO AMERICA; Mfr_part_number: RC0402JR-0710KL; Mistral Part No: 110009030208-R; Package: 0402; Part_type: RESISTORS\FIXED; Project: HSE; RoHS: Pb-Free; Temperature: -55°C+155°C; Tolerance: 5%; Voltage: NA; Wattage: 1/16W; Weight: 0.65mg; Datasheet: Y:\MIS_DATABASE\DATASHEETS\RESISTORS\YAGEO-RC0402.PDF
R323 R670 = RESISTOR: RES 100E 1/16W 5% 0402; Chkd/date: MANIRAJA/230817; Crtd /date: MANIRAJA/230817; Custom_Duty: 15%; Customs_HS_Code: 85332119; Distributor_name: DIGIKEY; Distributor_part_number: 541-100JCT-ND; Height: 0.40MM; Mfr_name: VISHAY; Mfr_part_number: CRCW0402100RJNED; Mistral Part No: 110009030164-R; Package: 0402; Part_type: RESISTORS\FIXED; Project: TI_MAXIE_CPB; RoHS: RoHS; Temperature: -55°C+155°C; Tolerance: 5%; Voltage: NA; Wattage: 1/16W; Weight: 0.65mg; Datasheet: Y:\MIS_DATABASE\DATASHEETS\RESISTORS\CRCW0603.PDF
R332 = RESISTOR: RES 220E 1/16W 5% 0402; Chkd/date: VASANTHA/291216; Crtd /date: GEETHA/260406; Custom_Duty: 15%; Customs_HS_Code: 85332119; Distributor_name: DIGIKEY; Distributor_part_number: P220JCT-ND; Footprint Path: Y:\MIS_DATABASE\Library\ALTIUM_TOOL\PCB_FOOTPRINTS\Altium_Footprint_Lib.PcbLib; Height: 0.40MM; Library Path: Y:\MIS_DATABASE\Library\ALTIUM_TOOL\SCHEMATICS_PARTS\MS_DISCRETE_Library.schlib; Mfr_name: PANASONIC-ECG; Mfr_part_number: ERJ-2GEJ221X; Mistral Part No: 110009030506-R; Package: 0402; Part_type: RESISTORS\FIXED; Project: RED EYE; RoHS: RoHS; Temperature: -55°C+155°C; Tolerance: 5%; Voltage: NA; Wattage: 1/16W; Weight: 0.8g/1000pcs; Datasheet: Y:\MIS_DATABASE\DATASHEETS\RESISTORS\ERJ12.PDF
R333 = RESISTOR: RES 30K 1/16W 5% 0402; Chkd/date: MANIRAJA/230817; Crtd /date: MANIRAJA/230817; Custom_Duty: 15%; Customs_HS_Code: 85332119; Distributor_name: DIGIKEY; Distributor_part_number: 541-30KJCT-ND; Height: 0.40MM; Mfr_name: VISHAY; Mfr_part_number: CRCW040230K0JNED; Mistral Part No: 110017080023-R; Package: 0402; Part_type: RESISTORS\FIXED; Project: TI_MAXIE_CPB; RoHS: RoHS; Temperature: -55°C+155°C; Tolerance: 5%; Voltage: NA; Wattage: 1/16W; Weight: 0.65mg; Datasheet: Y:\MIS_DATABASE\DATASHEETS\RESISTORS\CRCW0603.PDF
R334 = RESISTOR: RES 51K 1/16W 5% 0402; Chkd/date: MANIRAJA/230817; Crtd /date: MANIRAJA/230817; Custom_Duty: 15%; Customs_HS_Code: 85332119; Distributor_name: DIGIKEY; Distributor_part_number: 541-51KJCT-ND; Height: 0.40MM; Mfr_name: VISHAY; Mfr_part_number: CRCW040251K0JNED; Mistral Part No: 110009030966-R; Package: 0402; Part_type: RESISTORS\FIXED; Project: TI_MAXIE_CPB; RoHS: RoHS; Temperature: -55°C+155°C; Tolerance: 5%; Voltage: NA; Wattage: 1/16W; Weight: 0.65mg; Datasheet: Y:\MIS_DATABASE\DATASHEETS\RESISTORS\CRCW0603.PDF
R335 = RESISTOR: RES 180E 1/16W 5% 0402; Chkd/date: MAZHAR/150709; Crtd /date: GEETHA/280406; Custom_Duty: 15%; Customs_HS_Code: 85332119; Distributor_name: DIGIKEY; Distributor_part_number: P180JCT-ND; Footprint Path: Y:\MIS_DATABASE\Library\ALTIUM_TOOL\PCB_FOOTPRINTS\Altium_Footprint_Lib.PcbLib; Height: 0.40MM; Library Path: Y:\MIS_DATABASE\Library\ALTIUM_TOOL\SCHEMATICS_PARTS\MS_DISCRETE_Library.schlib; Mfr_name: PANASONIC-ECG; Mfr_part_number: ERJ-2GEJ181X; Mistral Part No: 110009030371-R; Package: 0402; Part_type: RESISTORS\FIXED; Project: RED EYE; RoHS: RoHS; Temperature: -55°C+155°C; Tolerance: 5%; Voltage: NA; Wattage: 1/16W; Weight: 0.8mg; Datasheet: Y:\MIS_DATABASE\DATASHEETS\RESISTORS\ERJ12.PDF
R653 = RESISTOR: RES 4.87K 1/16W 1% 0402; Chkd/date: MAZHAR/150709; Crtd /date: USMAN/150109; Custom_Duty: 15%; Customs_HS_Code: 85332119; Distributor_name: DIGIKEY; Distributor_part_number: P4.87KLCT-ND; Footprint Path: Y:\MIS_DATABASE\Library\ALTIUM_TOOL\PCB_FOOTPRINTS\Altium_Footprint_Lib.PcbLib; Height: 0.40MM; Library Path: Y:\MIS_DATABASE\Library\ALTIUM_TOOL\SCHEMATICS_PARTS\MS_DISCRETE_Library.schlib; Mfr_name: PANASONIC-ECG; Mfr_part_number: ERJ2RKF4871X; Mistral Part No: 110009030803-R; Package: 0402; Part_type: RESISTORS\FIXED; Project: BSN-II; RoHS: RoHS; Temperature: -55°C+155°C; Tolerance: 1%; Voltage: NA; Wattage: 1/16W; Weight: 0.8mg; Datasheet: Y:\MIS_DATABASE\DATASHEETS\RESISTORS\PAN-ERJSERIES.PDF
R657 = RESISTOR: RES 51E 1/16W 5% 0402; Chkd/date: SHREESHAIL/131205; Crtd /date: MAZHAR/120505; Custom_Duty: 15%; Customs_HS_Code: 85332119; Distributor_name: DIGIKEY; Distributor_part_number: P51JTR-ND; Height: 0.40MM; Mfr_name: PANASONIC-ECG; Mfr_part_number: ERJ-2GEJ510X; Mistral Part No: 110009030962-R; Package: 0402; Part_type: RESISTORS\FIXED; Project: CTP02_REVA_BASE; RoHS: RoHS; Tolerance: 5%; Wattage: 1/16W; Datasheet: Y:\MIS_DATABASE\DATASHEETS\RESISTORS\ERJ12.PDF
R677 = RESISTOR: RES 220K 1/16W 1% 0402; Chkd/date: MANIRAJA/230817; Crtd /date: MANIRAJA/230817; Custom_Duty: 15%; Customs_HS_Code: 85332119; Distributor_name: DIGIKEY; Distributor_part_number: 541-220KLCT-ND; Height: 0.40MM; Mfr_name: VISHAY; Mfr_part_number: CRCW0402220KFKED; Mistral Part No: 110017080025-R; Package: 0402; Part_type: RESISTORS\FIXED; Project: TI_MAXIE_CPB; RoHS: RoHS; Temperature: -55°C+155°C; Tolerance: 1%; Voltage: NA; Wattage: 1/16W; Weight: 0.65mg; Datasheet: Y:\MIS_DATABASE\DATASHEETS\RESISTORS\CRCW0603.PDF
R678 = RESISTOR: RES 330K 1/16W 1% 0402; Chkd/date: MANIRAJA/230817; Crtd /date: MANIRAJA/230817; Custom_Duty: 15%; Customs_HS_Code: 85332119; Distributor_name: DIGIKEY; Distributor_part_number: 541-330KLCT-ND; Footprint Path: Y:\MIS_DATABASE\Library\ALTIUM_TOOL\PCB_FOOTPRINTS\Altium_Footprint_Lib.PcbLib; Height: 0.40MM; Library Path: Y:\MIS_DATABASE\Library\ALTIUM_TOOL\SCHEMATICS_PARTS\MS_DISCRETE_Library.schlib; Mfr_name: VISHAY; Mfr_part_number: CRCW0402330KFKED; Mistral Part No: 110017080024-R; Package: 0402; Part_type: RESISTORS\FIXED; Project: TI_MAXIE_CPB; RoHS: RoHS; Temperature: -55°C+155°C; Tolerance: 1%; Voltage: NA; Wattage: 1/16W; Weight: 0.65mg; Datasheet: Y:\MIS_DATABASE\DATASHEETS\RESISTORS\CRCW0603.PDF
U57 = TPS79601DRBR_SON8: IC 1A HIGH PSRR RF ADJ LDO LINEAR REGULATOR SON8; Chkd/date: MANIRAJA/030518; Crtd /date: MAZHAR/280809; Custom_Duty: 15%; Customs_HS_Code: 85423100; Distributor_name: DIGIKEY; Distributor_part_number: 296-23107-1-ND; Footprint Path: Y:\MIS_DATABASE\Library\ALTIUM_TOOL\PCB_FOOTPRINTS\Altium_Footprint_Lib.PcbLib; Height: 1.00MM; Library Path: Y:\MIS_DATABASE\Library\ALTIUM_TOOL\SCHEMATICS_PARTS\MS_MISCPOWER_Library.schlib; Mfr_name: TEXAS INSTRUMENTS; Mistral Part No: 142009080012-R; Package: SON8; Part_type: ICS\POWER\VOLTAGE REGULATOR; Project: DIO_TXRX; RoHS: RoHS; Temperature: -40°C+125°C; Tolerance: NA; Voltage: NA; Wattage: NA; Weight: 24mg; Datasheet: Y:\MIS_DATABASE\DATASHEETS\MISC\REGULATORS\TPS796XX.PDF
U58 = TPD4E004_SON6: IC 4CH ESD-PROT ARRAY SON6; Chkd/date: SUHAS/131210; Crtd /date: MUDDU/010310; Custom_Duty: 15%; Customs_HS_Code: 85423100; Distributor_name: DIGIKEY; Distributor_part_number: 296-23618-1-ND; Height: 0.60MM; Mfr_name: TEXAS INSTRUMENTS; Mistral Part No: 141010020012-P; Package: SON6; Part_type: ICS\INTERFACE; Project: BUG_BASE-II; RoHS: Pb-Free; Temperature: -40°C+85°C; Weight: NA; Datasheet: Y:\MIS_DATABASE\DATASHEETS\ICS\INTERFACE\TPD4E004.PDF
U106 = TM4C1294NCPDTT3R_TQFP128: IC 32-BIT MICROCONTROLLER WITH 1MB FLASH TQFP128; Chkd/date: MANIRAJA/220817; Crtd /date: MANIRAJA/220817; Custom_Duty: 15%; Customs_HS_Code: 85423100; Distributor_name: DIGIKEY; Distributor_part_number: TM4C1294NCPDTT3R-ND; Height: 1.20MM; Mfr_name: TEXAS INSTRUMENTS; Mistral Part No: 141217080002-R; Package: TQF9128; Part_type: ICS\DIGITAL\MICROCONTROLLER; Project: TI_MAXIE_CPB; RoHS: RoHS; Temperature: -40°C+105°C; Tolerance: NA; Voltage: NA; Wattage: NA; Weight: 503.5mg; Datasheet: Y:\MIS_DATABASE\DATASHEETS\ICS\DIGITAL\MICROCONTROLLER\TM4C1294NCPD.PDF
U107 = LM4040B25IDCKR_SC70-5: IC PRECISION MICROPOWER SHUNT VOLTAGE REFERENCE SC70-5; Chkd/date: MANIRAJA/230817; Crtd /date: MANIRAJA/230817; Custom_Duty: 15%; Customs_HS_Code: 85423100; Distributor_name: DIGIKEY; Distributor_part_number: 296-20873-1-ND; Height: 1.10MM; Mfr_name: TEXAS INSTRUMENTS; Mistral Part No: 142017080015-R; Package: SC70-5; Part_type: ICS\POWER\VOLTAGE REGULATOR; Project: TI_MAXIE_CPB; RoHS: RoHS; Temperature: -40°C+85°C; Tolerance: NA; Voltage: NA; Wattage: NA; Weight: 30mg; Datasheet: Y:\MIS_DATABASE\DATASHEETS\ICS\POWER\LM4040B25I.PDF
Y6 = CRY4_13: CRY 16.000MHz SMD; Chkd/date: MANIRAJA/230817; Crtd /date: MANIRAJA/230817; Custom_Duty: 24%; Customs_HS_Code: 85439000; Distributor_name: DIGIKEY; Distributor_part_number: 644-1157-1-ND; Height: 0.90MM; Mfr_name: NDK; Mfr_part_number: NX3225GA-16.000M-STD-CRG-1; Mistral Part No: 130017080024-R; Package: SMD; Part_type: CRYSTAL; Project: TI_MAXIE_CPB; RoHS: RoHS; Temperature: -40°C+85°C; Tolerance: NA; Voltage: NA; Wattage: NA; Weight: NA; Datasheet: Y:\MIS_DATABASE\DATASHEETS\MISC\CRY_OSC\NX3225GA.PDF
R241 R623 = RESISTOR: RES 22E 1/16W 1% 0402; Alternate_mfr_name_A: VISHAY; Alternate_mfr_part_number_A: CRCW040222R0FKED; Chkd/date: SUHAS/290910; Crtd /date: MAZHAR/090909; Cust_part_number: 4700-80047E; Custom_Duty: 15%; Customs_HS_Code: 85332119; Distributor_name: DIGIKEY; Distributor_name_A: DIGIKEY; Distributor_part_number: 311-22.0LRCT-ND; Distributor_part_number_A: 541-22.0LCT-ND; Height: 0.40MM; Mfr_name: YAGEO AMERICA; Mfr_part_number: RC0402FR-0722RL; Mistral Part No: 110009090004-P; Package: 0402; Part_type: RESISTORS\FIXED; Project: VMEFMCD; Remarks: In alternate datasheet it is RoHS COMPLIANT. Y:\MIS_DATABASE\DATASHEETS\RESISTORS\CRCW0402.PDF; RoHS: Pb-Free; SIGNAL_MODEL: RESISTOR_RES0402_22E_22E; Temperature: -55°C+155°C; Tolerance: 1%; Voltage: 50V; Wattage: 1/16W; Weight: 0.8g/1000pcs; Datasheet: Y:\MIS_DATABASE\DATASHEETS\RESISTORS\YAGEO-RC0402.PDF
U36 = SN74LVC1G04DCKR_SC70-5: IC SINGLE INVERTER GATE SC70-5; Chkd/date: SUHAS/221010; Crtd /date: USMAN/150709; Custom_Duty: 15%; Customs_HS_Code: 85423100; Distributor_name: DIGIKEY; Distributor_part_number: 296-11600-1-ND; Height: 1.10MM; Mfr_name: TEXAS INSTRUMENTS; Mistral Part No: 141009070007-R; Part_type: ICS\DIGITAL\GATES; Project: BUG_BASE-II; RoHS: Sb/ Br FREE; Temperature: -40°C+85°C; Datasheet: Y:\MIS_DATABASE\DATASHEETS\ICS\DIGITAL\GATES\SN74LVC1G04-1.PDF
U43 U98 = SN74AVC4T245RGYR_QFN16: IC 4-BIT DUAL SUPPLY BUS TRANSCEIVER QFN16; Chkd/date: MAZHAR/060308; Crtd /date: USMAN/060308; Custom_Duty: 15%; Customs_HS_Code: 85423100; Distributor_name: DIGIKEY; Distributor_part_number: 296-18231-1-ND; Height: 1.00MM; Mfr_name: TEXAS INSTRUMENTS; Mistral Part No: 141009030112-R; Package: QFN16; Part_type: ICS\DIGITAL\COMBINATIONAL; Project: HS100RD; RoHS: Sb/ Br FREE; Datasheet: Y:\MIS_DATABASE\DATASHEETS\ICS\DIGITAL\BUSTRANSCEIVER\SN74AVC4T245XXXX.PDF
U87 U103 = TXS0102DCUR_VSSOP8: IC 2BIT BI-DIR VOLTAGE-LEVEL TRANSLATOR US8(VSSOP8); Chkd/date: MANIRAJA/130617; Crtd /date: SHREESHAIL/190108; Custom_Duty: 15%; Customs_HS_Code: 85423100; Distributor_name: DIGIKEY; Distributor_part_number: 296-21931-1-ND; Footprint Path: Y:\MIS_DATABASE\Library\ALTIUM_TOOL\PCB_FOOTPRINTS\Altium_Footprint_Lib.PcbLib; Height: 0.90MM; Library Path: Y:\MIS_DATABASE\Library\ALTIUM_TOOL\SCHEMATICS_PARTS\MS_MISCINTERFACE_Library.schlib; Mfr_name: TEXAS INSTRUMENTS; Mistral Part No: 141009030376-R; Package: US8; Part_type: ICS\INTERFACE\LEVEL TRANSLATOR; Project: SD_WATERLOO; RoHS: RoHS; Temperature: -40°C+85°C; Tolerance: NA; Voltage: NA; Wattage: NA; Weight: 9.6mg; Datasheet: Y:\MIS_DATABASE\DATASHEETS\ICS\INTERFACE\TXS0102.PDF
U97 U101 = SN74AVC2T244DQMR_X2SON8: IC 2-BIT UNDIRECTIONAL VOLTAGE-LEVEL TRANSLATOR X2SON8; Chkd/date: VASANTHA/060516; Crtd /date: VASANTHA/030316; Customs_HS_Code: 15%; Distributor_name: DIGIKEY; Distributor_part_number: 296-29674-1-ND; Height: 0.40MM; Mfr_name: TEXAS INSTRUMENTS; Mistral Part No: 141016030002-R; Package: X2SON8; Part_type: ICS\INTERFACE\LEVEL TRANSLATOR; Pb-Free: 85423100; Project: OCTASIC_3600; RoHS: RoHS; Temperature: -40°C+85°C; Tolerance: NA; Voltage: NA; Wattage: NA; Weight: NA; Datasheet: Y:\MIS_DATABASE\DATASHEETS\ICS\INTERFACE\SN74AVC2T244.PDF

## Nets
DGND: C6.2 C18.2 C148.2 C189.2 C219.2 C225.2 C226.2 C250.2 C251.2 C263.2 C276.2 C277.2 C278.2 C287.2 C288.2 C289.2 C294.2 C302.2 C304.2 C395.2 C581.2 C591.2 C604.2 C610.2 C611.2 C615.2 C616.2 C621.2 C626.2 C629.2 C633.2 C634.2 C642.2 C645.2 C646.2 C647.2 C650.2 C651.2 C652.1 C653.2 C654.2 C655.2 C657.2 C659.1 C660.2 C665.2 C667.2 C668.2 C669.2 FL6.2 J21.3 J23.5(GND) J34.8 J34.10 J34.12 J34.16 J34.20 J40.3 J40.5 J40.9 LD19.1(CATHODE) LD20.1(CATHODE) R130.2 R216.2 R254.1 R312.1 R315.1 R324.2 R333.2 R621.1 R639.1 R641.2 R650.1 R652.1 R653.2 R677.2 U2.7(GND) U3.1(A1) U3.7(GND) U27.1(A1) U27.7(GND) U36.3(GND) U43.8(GND1) U43.9(GND2) U43.17(PAD) U57.6(GND) U57.9(PAD) U58.3(GND) U67.1(A1) U67.7(GND) U68.1(A1) U68.2(A0) U68.7(GND) U69.7(GND) U70.7(GND) U87.2(GND) U93.2(A0) U93.7(GND) U97.3(A2) U97.5(GND) U97.6(B2) U98.8(GND1) U98.9(GND2) U98.17(PAD) U101.3(A2) U101.5(GND) U101.6(B2) U103.2(GND) U106.10(GNDA) U106.17(GND) U106.48(GND) U106.55(GND) U106.58(GND) U106.64(~{WAKE}) U106.66(XOSC0) U106.80(GND) U106.114(GND) U107.1(ANODE) Y6.2 Y6.4 ; also on sheet 11 12 13 14 15 16 17 18 19 20 21 22 23 24 25 29 30 31 32 33 34 35 36 37 38 39 40 41 42 43 44
VCC1V1: C276.1 C277.1 J26.1 J27.1 R349.4 R355.3 ; also on sheet 41
VCC1V2_DDR: C287.1 C288.1 J28.1 J29.1 R360.4 R361.1 ; also on sheet 41
VCC1V8: C219.1 J15.1 R234.2 ; also on sheet 11 18 19 20 21 22 23 29 31 33 35 36 37 38 41 44
VCC3V3_IO: C6.1 C18.1 C148.1 C189.1 C225.1 C226.1 C289.1 C294.1 C302.1 C304.1 C395.1 C581.1 C591.1 C604.1 C610.1 C615.1 C626.1 C629.1 C634.1 J31.1 R147.2 R215.2 R459.2 R504.1 R521.1 R592.1 R593.1 U2.1(A1) U2.2(A0) U2.6(VS+) U3.6(VS+) U27.6(VS+) U36.5(VCC) U43.1(VCCA) U43.16(VCCB) U67.2(A0) U67.6(VS+) U68.6(VS+) U69.1(A1) U69.6(VS+) U70.1(A1) U70.6(VS+) U87.3(VCCA) U87.7(VCCB) U93.1(A1) U93.6(VS+) U97.1(VCCA) U98.1(VCCA) U101.1(VCCA) U101.8(VCCB) U103.3(VCCA) ; also on sheet 11 18 19 20 21 22 23 24 25 29 30 31 33 34 35 36 37 38 39 41 42 43 44
VCC3V3_XDS: C249.1 C251.1 C611.1 C616.1 C621.1 C633.1 C642.1 C646.1 C647.1 C650.1 C657.1 C660.1 C668.1 C669.1 J34.5 J40.1 R313.2 R314.2 R322.2 R334.1 R649.2 R651.2 R654.1 R655.1 R657.2 R663.1 U57.3(OUT1) U57.4(OUT2) U97.8(VCCB) U98.16(VCCB) U103.7(VCCB) U106.7(VDD) U106.8(VDDA) U106.16(VDD) U106.26(VDD) U106.28(VDD) U106.39(VDD) U106.47(VDD) U106.51(VDD) U106.52(VDD) U106.69(VDD) U106.79(VDD) U106.90(VDD) U106.101(VDD) U106.113(VDD) U106.122(VDD)
VDD_CORE: J27.2 R355.2 ; also on sheet 12 13 39 41
VDD_DDR4: J28.2 R360.1 ; also on sheet 16 17 42
VDD_MCU: J26.2 R349.1 ; also on sheet 12 13
VDD_MPU: J24.2 R348.1 ; also on sheet 12 39 41
VDDA1V8: C263.1 J25.1 R342.2 ; also on sheet 41
VDDA_1V8: J25.2 R342.3 ; also on sheet 13
VDDC_1V2: C651.1 C653.1 C667.1 U106.87(VDDC) U106.115(VDDC)
INA_ALERT: J21.4 R14.2 R18.2 R147.1 R148.2 R358.2 R363.2 R364.2 R365.2 R591.2
JTAG_DIR: R254.2 U43.2(1DIR) U43.3(2DIR)
JTAG_EMU0: R504.2 U87.8(B1) ; also on sheet 29
JTAG_EMU1: R521.2 U87.1(B2) ; also on sheet 29
JTAG_TCK: U43.12(1B2) ; also on sheet 29
JTAG_TDI: U43.13(1B1) ; also on sheet 29
JTAG_TDO: U101.7(B1) ; also on sheet 29
JTAG_TMS: U43.11(2B1) ; also on sheet 29
JTAG_TRST#: U43.10(2B2) ; also on sheet 29
MCU_RTCK: J34.9 R617.2
MCU_TCK: J34.11 R610.2
MCU_TCLK: R610.1 R615.2 R617.1
MCU_TDI: J34.3 R619.2
MCU_TDIS: J34.4 R639.2
MCU_TDO: J34.7 R618.2
MCU_TMS: J34.1 R620.2
MCU_TRST#: J34.2 R640.2 R641.1
MCU_XDS110_TCK: R609.1 R615.1 U106.35(PA2/SSI0CLK)
MCU_XDS110_TDI: R612.1 R619.1 U106.38(PA5/SSI0XDAT1)
MCU_XDS110_TDO: R611.1 R618.1 U106.37(PA4/SSI0XDAT0)
MCU_XDS110_TMS: R613.1 R620.1 U106.36(PA3/SSI0FSS)
MCU_XDS110_TRST#: R640.1 R646.1 U106.40(PA6)
OSC0: C652.2 U106.88(OSC0) Y6.1
OSC1: C659.2 U106.89(OSC1) Y6.3
SEL_XDS: U36.4(Y) U87.6(OE) U97.4(~{OE}) U98.14(~{2OE}) U98.15(~{1OE})
SEL_XDS110_INV: R215.1 R216.1 U36.2(A) U43.14(~{2OE}) U43.15(~{1OE}) U101.4(~{OE}) U103.6(OE) ; also on sheet 29
SOC_DVDD1V8: J15.2 R234.3 ; also on sheet 13 14 18 38
SoC_DVDD3V3: J31.2 R459.3 ; also on sheet 13 14 34
SoC_EMU0: U87.5(A1) U103.5(A1) ; also on sheet 34
SoC_EMU1: U87.4(A2) U103.4(A2) ; also on sheet 34
SoC_I2C2_SCL: R325.1 R592.2 U2.5(SCL) U3.5(SCL) U27.2(A0) U27.5(SCL) U67.5(SCL) U68.5(SCL) U69.2(A0) U69.5(SCL) U70.5(SCL) U93.5(SCL) ; also on sheet 20 24 44
SoC_I2C2_SDA: R326.1 R593.2 U2.4(SDA) U3.2(A0) U3.4(SDA) U27.4(SDA) U67.4(SDA) U68.4(SDA) U69.4(SDA) U70.2(A0) U70.4(SDA) U93.4(SDA) ; also on sheet 20 24 44
SoC_MPU: C278.1 J24.1 R348.4 ; also on sheet 41
SoC_TCK: R241.2 R623.2 ; also on sheet 34
SoC_TDI: U43.4(1A1) U98.4(1A1) ; also on sheet 34
SoC_TDO: U97.2(A1) U101.2(A1) ; also on sheet 34
SoC_TMS: U43.6(2A1) U98.6(2A1) ; also on sheet 34
SoC_TRST#: R130.1 U43.7(2A2) U98.7(2A2) ; also on sheet 34
SoC_VDDS_DDR: J29.2 R361.4 ; also on sheet 12
TM4C129_RSTn: J40.10 R323.2
TM4C129_TCK: J40.4 U106.100(PC0/TCK/SWCLK)
TM4C129_TDI: J40.8 U106.98(PC2/TDI)
TM4C129_TDO: J40.6 U106.97(PC3/TDO/SWO)
TM4C129_TMS: J40.2 U106.99(PC1/TMS/SWDIO)
VREF: C654.1 C655.1 R663.2 U106.9(VREFA+) U107.3(CATHODE)
XDS110_DIR: R621.2 U98.2(1DIR) U98.3(2DIR)
XDS110_EMU0: R655.2 U103.8(B1) U106.42(PF0)
XDS110_EMU1: R654.2 U103.1(B2) U106.43(PF1)
XDS110_TCK: R609.2 U98.12(1B2)
XDS110_TDI: R612.2 U98.13(1B1)
XDS110_TDO: R611.2 U97.7(B1)
XDS110_TMS: R613.2 U98.11(2B1)
XDS110_TRST#: R646.2 U98.10(2B2)
XDS_SHIELD: FL6.1 J23.SH1 J23.SH2 J23.SH3 J23.SH4 J23.SH5 J23.SH6
XDS_USB_DM: J23.2(D-) U58.5(IO4) U106.93(PL7/USB0DM)
XDS_USB_DP: J23.3(D+) U58.4(IO3) U106.94(PL6/USB0DP)
XDS_USB_ID: J23.4(ID) R665.2 U58.2(IO2)
XDS_USB_VBUS: C250.1 J23.1(VBUS) R670.1 R678.1 U57.1(IN1) U57.2(IN2) U57.8(EN) U58.6(VCC)
N15202140: R665.1 U106.95(PB0/USB0ID)
N15204440: C249.2 R333.1 R334.2 U57.5(NR/FB)
N15205319: C645.1 R657.1 U106.68(VBAT)
N15205492: R322.1 R323.1 R324.1 U106.70(~{RST})
N15212041: R653.1 U106.59(RBAIS)
N15239696: C665.1 R670.2 U106.96(PB1/USB0VBUS)
N15241750: R677.1 R678.2 U106.1(PD0/AIN15)
N15242949: R335.1 U106.3(PD2/AIN13)
N15242980: LD20.2(ANODE) R335.2
N15243226: R332.1 U106.4(PD3/AIN12)
N15854221: C440.2 R715.1 U27.8(VBUS) U27.9(VIN-)
N15854243: C440.1 R714.1 U27.10(VIN+)
N15854325: R148.1 U27.3(ALERT)
N15854335: R18.1 U3.3(ALERT)
N15854337: C279.2 R713.1 U3.8(VBUS) U3.9(VIN-)
N15854349: C279.1 R712.1 U3.10(VIN+)
N15854407: R363.1 U68.3(ALERT)
N15854417: C286.2 R709.1 U68.8(VBUS) U68.9(VIN-)
N15854427: C286.1 R708.1 U68.10(VIN+)
N15854463: R358.1 U67.3(ALERT)
N15854467: C280.2 R711.1 U67.8(VBUS) U67.9(VIN-)
N15854483: C280.1 R710.1 U67.10(VIN+)
N15854545: R591.1 U93.3(ALERT)
N15854547: R14.1 U2.3(ALERT)
N15854553: C218.2 R717.1 U93.8(VBUS) U93.9(VIN-)
N15854557: C273.2 R719.1 U2.8(VBUS) U2.9(VIN-)
N15854581: C273.1 R718.1 U2.10(VIN+)
N15854603: C218.1 R716.1 U93.10(VIN+)
N15854669: R364.1 U69.3(ALERT)
N15854673: C292.2 R723.1 U69.8(VBUS) U69.9(VIN-)
N15854685: C292.1 R722.1 U69.10(VIN+)
N15854737: R365.1 U70.3(ALERT)
N15854741: C293.2 R721.1 U70.8(VBUS) U70.9(VIN-)
N15854757: C293.1 R720.1 U70.10(VIN+)
N15854857: J21.2 R326.2
N15854859: J21.1 R325.2
N16679303: R312.2 R313.1 U106.60(PK7)
N16679944: R649.1 R650.2 U106.63(PK4)
N16679981: R651.1 R652.2 U106.61(PK6)
N16680014: R314.1 R315.2 U106.62(PK5)
N16937764: R241.1 U43.5(1A2)
N16938293: R623.1 U98.5(1A2)
N17682848: R355.4 R708.2
N17682861: R355.1 R709.2
N17683733: R349.3 R710.2
N17683748: R349.2 R711.2
N17685192: R348.3 R712.2
N17685207: R348.2 R713.2
N17685595: R459.1 R714.2
N17685608: R459.4 R715.2
N17685678: R234.1 R716.2
N17685693: R234.4 R717.2
N17685736: R342.1 R718.2
N17685749: R342.4 R719.2
N17686321: R361.2 R720.2
N17686333: R361.3 R721.2
N17686697: R360.3 R722.2
N17686710: R360.2 R723.2
N24658557: LD19.2(ANODE) R332.2

Not connected (* = marked no-connect by the designer): J21 5*; J34 6* 13* 14* 15* 17* 18* 19*; J40 7*; U36 1(NC)*; U57 7(NC)*; U58 1(IO1)*; U106 2(PD1/AIN14)* 5(PQ0)* 6(PQ1)* 11(PQ2)* 12(PE3/AIN0)* 13(PE2/AIN1)* 14(PE1/AIN2)* 15(PE0/AIN3)* 18(PK0/AIN16)* 19(PK1/AIN17)* 20(PK2/AIN18)* 21(PK3/AIN19)* 22(PC7/C0-)* 23(PC6/C0+)* 24(PC5/C1+)* 25(PC4/C1-)* 27(PQ3)* 29(PH0)* 30(PH1)* 31(PH2)* 32(PH3)* 33(PA0/U0RX)* 34(PA1/U0TX)* 41(PA7)* 44(PF2)* 45(PF3)* 46(PF4)* 49(PG0)* 50(PG1)* 53(EN0RXIN)* 54(EN0RXIP)* 56(EN0RX0N)* 57(EN0RX0P)* 65(~{HIB})* 67(XOSC1)* 71(PM7)* 72(PM6)* 73(PM5)* 74(PM4)* 75(PM3)* 76(PM2)* 77(PM1)* 78(PM0)* 81(PL0)* 82(PL1)* 83(PL2)* 84(PL3)* 85(PL4)* 86(PL5)* 91(PB2/I2C0SCL)* 92(PB3/I2C0SDA)* 102(PQ4)* 103(PP2)* 104(PP3)* 105(PP4)* 106(PP5)* 107(PN0)* 108(PN1)* 109(PN2)* 110(PN3)* 111(PN4)* 112(PN5)* 116(PJ0)* 117(PJ1)* 118(PP0/C2+)* 119(PP1/C2-)* 120(PB5/AIN11)* 121(PB4/AIN10)* 123(PE4/AIN9)* 124(PE5/AIN8)* 125(PD4/AIN7)* 126(PD5/AIN6)* 127(PD6/AIN5)* 128(PD7/AIN4)*; U107 2(NC1)* 4(NC2)* 5(NC3)*

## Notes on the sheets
sheet 26
- CURRENT MONITORING  DEVICES
- VDD_CORE
- SoC_DVDD1V8
- I2C ADDRESS: 0x40
- I2C ADDRESS: 0x44
- VDD_MCU
- SoC_AVDD1V8
- I2C ADDRESS: 0x41
- I2C ADDRESS: 0x45
- VDD_MPU
- SoC_VDDS_DDR
- INA I2C SLAVE ADDRESS
- SLAVE
  ADDRESS
  (IN HEX)
- SUPPLY NET
- POWER SOURCE
- I2C ADDRESS: 0x42
- VCC1V0
- VDD_CORE
- 40
- VDD_MCU
- 41
- I2C ADDRESS: 0x46
- VCC1V0
- SoC_MPU
- VDD_MPU
- 42
- VCC3V3_IO
- SoC_DVDD3V3
- 43
- VDD_DDR
- VCC1V8
- SoC_DVDD1V8
- 44
- SoC_DVDD3V3
- VDDA1V8
- SoC_AVDD1V8
- 45
- VCC1V2_DDR
- SoC_VDDS_DDR
- 46
- VCC1V2_DDR
- VDD_DDR
- 47
- I2C ADDRESS: 0x47
- I2C ADDRESS: 0x43
sheet 27
- XDS110 POWER
- CTI 20 Pin Header external probe
- USB Connector
- XDS110 DEBUGGER
- 10-PIN PLUG-OF-NAILS
- This will indicate the unique ID of the Debugger
- 0- Ohm Res MUX between XDS110 JTAG  and  MCU cTI 20  pin connector.
  -For  XDS110 JTAG  R609,R613,R611,R612 and R646 Should be installed and R615,R620,R618,R619 and R640 Should be DNI'd.
  -For  MCU cTI 20  pin , R615,R620,R618,R619 and R640 Should be Installed and R609,R613,R611,R612 and R646 Should be DNI'd.
sheet 28
- JTAG BUFFER
- BUFFER XDS110
- BUFFER 20 PIN JTAG
- JTAG-DIR = H: A -> B
  JTAG_DIR = L: B -> A
  OE = H: output = Hi-Z
- XDS110_DIR = H: A -> B
  XDS110_DIR = L: B -> A
  OE = H: output = Hi-Z
